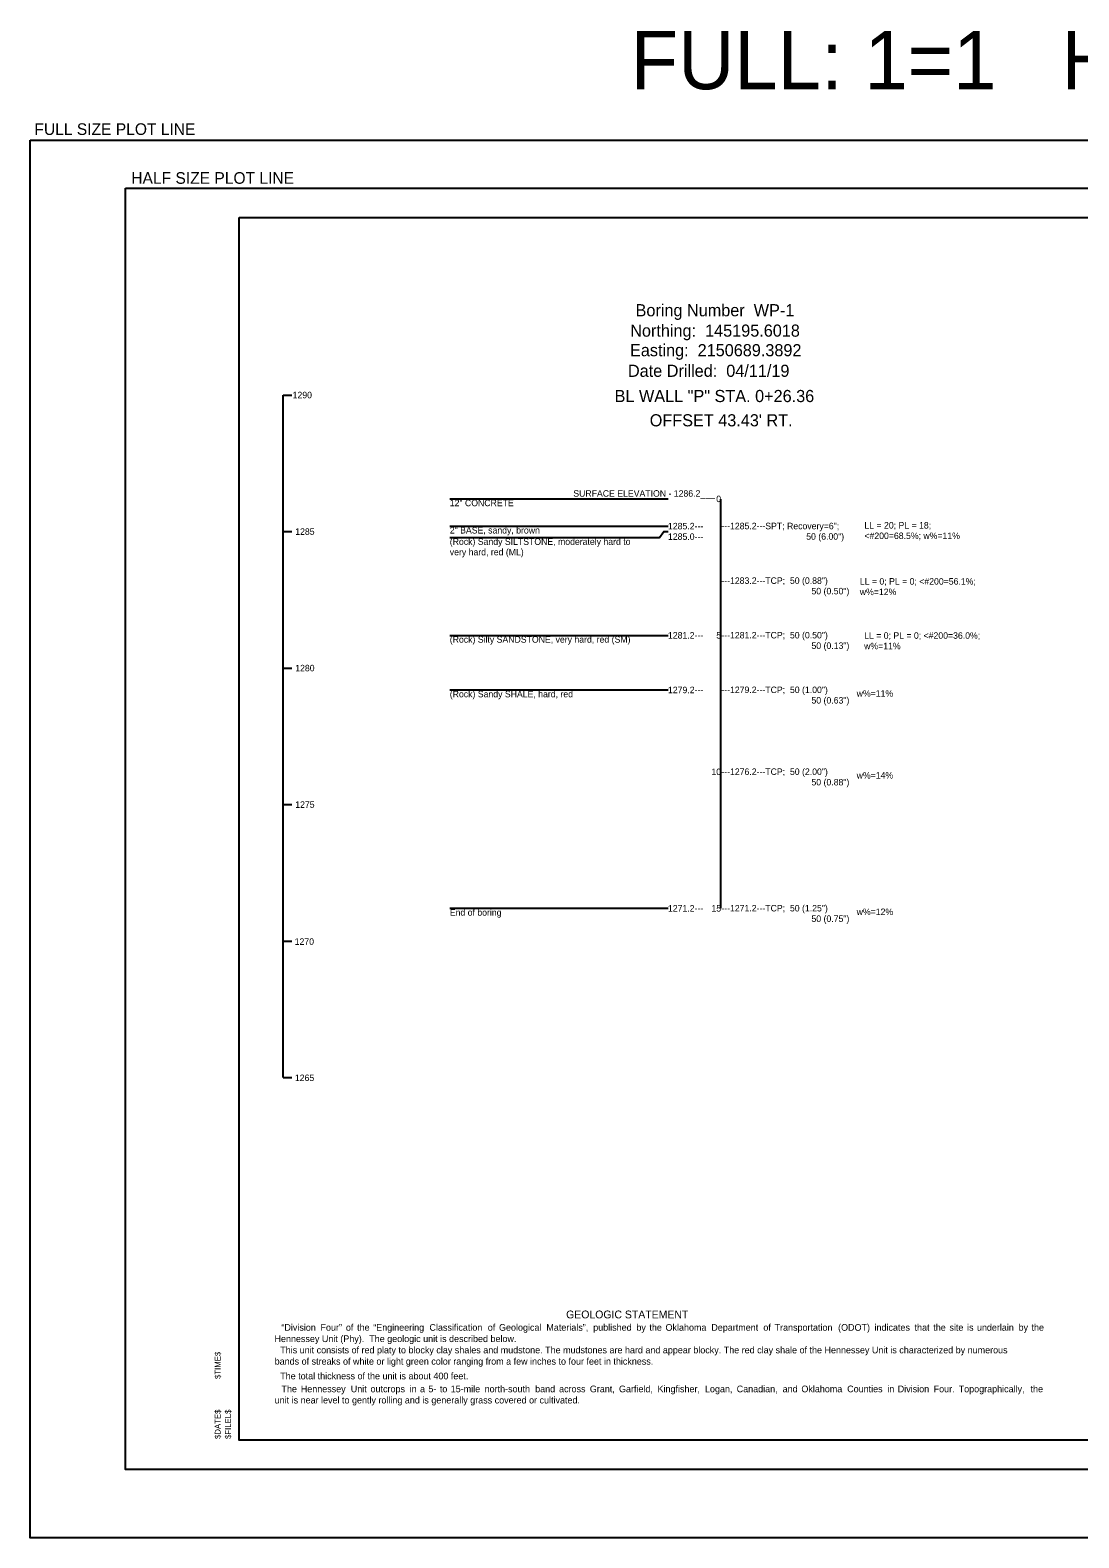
# Model space of a CAD drawing. Extents: x 6.6 to 42.6, y 24.1 to 55.9.
# Drawn here: x 6.62 to 24.62, y 29.97 to 55.86 of the extents above; entities that cross this region are included whole.
import ezdxf

# ---------------------------------------------------------------- set-up
doc = ezdxf.new("R2010")
doc.units = 0
for name, color, linetype in [('S', 7, 'Continuous'), ('SHT_Plot_Shape_Full', 7, 'Continuous'), ('SHT_Plot_Shape_Half', 7, 'Continuous'), ('SHT_Plot_Stamp', 7, 'Continuous'), ('SHT_Sheet_Border', 7, 'Continuous'), ('Text', 7, 'Continuous')]:
    doc.layers.add(name, color=color, linetype=linetype)

# ---------------------------------------------------------------- blocks, each defined once
blk = doc.blocks.new('Stamp_Plot_Stamp')
at = {"layer": 'SHT_Plot_Stamp'}
for s, p in [('$TIME$', (1.695, 1.572)), ('$DATE$', (1.695, 0.542)), ('$FILEL$', (1.873, 0.542))]:
    blk.add_text(s, height=0.1, rotation=90, dxfattribs=at).set_placement(p)

msp = doc.modelspace()

# ---------------------------------------------------------------- linework, layer by layer
msp.add_line((10.966, 37.876), (10.966, 49.594))
for points in [[(10.966, 49.594), (11.116, 49.594)], [(13.827, 47.813), (17.577, 47.813)], [(18.472, 47.81), (18.472, 40.782)], [(10.966, 47.251), (11.116, 47.251)], [(13.827, 47.344), (17.577, 47.344)], [(13.827, 47.149), (17.427, 47.149), (17.502, 47.251), (17.577, 47.251)], [(13.827, 45.469), (17.577, 45.469)], [(10.966, 44.907), (11.116, 44.907)], [(13.827, 44.532), (17.577, 44.532)], [(10.966, 42.563), (11.116, 42.563)], [(13.827, 40.782), (17.577, 40.782)], [(10.966, 40.219), (11.116, 40.219)], [(10.966, 37.876), (11.116, 37.876)]]:
    msp.add_lwpolyline(points)
at = {"layer": 'SHT_Plot_Shape_Full'}
msp.add_lwpolyline([(6.624, 53.971), (42.624, 53.971), (42.624, 29.971), (6.624, 29.971)], close=True, dxfattribs=at)
at = {"layer": 'SHT_Plot_Shape_Half'}
msp.add_lwpolyline([(8.262, 53.146), (42.262, 53.146), (42.262, 31.146), (8.262, 31.146)], close=True, dxfattribs=at)
at = {"layer": 'SHT_Sheet_Border'}
msp.add_lwpolyline([(10.212, 52.646), (41.712, 52.646), (41.712, 31.646), (10.212, 31.646)], close=True, dxfattribs=at)

# ---------------------------------------------------------------- block references
at = {"layer": 'SHT_Plot_Stamp'}
msp.add_blockref('Stamp_Plot_Stamp', (8.198, 31.127), dxfattribs=at)

# ---------------------------------------------------------------- texts
for s, height, p in [('Boring Number  WP-1', 0.2083, (17.016, 50.948)), ('Northing:  145195.6018', 0.20832, (16.924, 50.598)), ('Easting:  2150689.3892', 0.20832, (16.92, 50.262)), ('Date Drilled:  04/11/19', 0.20832, (16.885, 49.908)), ('1290', 0.1116, (11.129, 49.54)), ('BL WALL "P" STA. 0+26.36', 0.20832, (16.656, 49.475)), ("OFFSET 43.43' RT.", 0.20832, (17.259, 49.058)), ('SURFACE ELEVATION - 1286.2___', 0.1116, (15.947, 47.85)), ('12" CONCRETE', 0.1116, (13.827, 47.687)), ('0', 0.112, (18.401, 47.757)), ('1285.2---', 0.1116, (17.572, 47.289)), ('---1285.2---SPT; Recovery=6";', 0.1116, (18.488, 47.291)), ('LL = 20; PL = 18;', 0.1116, (20.944, 47.303)), ('1285', 0.1116, (11.174, 47.195)), ('2" BASE, sandy, brown', 0.1116, (13.827, 47.218)), ('(Rock) Sandy SILTSTONE, moderately hard to', 0.1116, (13.827, 47.023)), ('1285.0---', 0.1116, (17.572, 47.109)), ('50 (6.00")', 0.1116, (19.945, 47.111)), ('<#200=68.5%; w%=11%', 0.1116, (20.944, 47.123)), ('very hard, red (ML)', 0.1116, (13.827, 46.843)), ('---1283.2---TCP;  50 (0.88")', 0.1116, (18.488, 46.353)), ('LL = 0; PL = 0; <#200=56.1%;', 0.1116, (20.865, 46.34)), ('50 (0.50")', 0.1116, (20.035, 46.173)), ('w%=12%', 0.1116, (20.865, 46.16)), ('(Rock) Silty SANDSTONE, very hard, red (SM)', 0.1116, (13.827, 45.343)), ('1281.2---', 0.1116, (17.572, 45.414)), ('5', 0.112, (18.401, 45.414)), ('---1281.2---TCP;  50 (0.50")', 0.1116, (18.488, 45.416)), ('50 (0.13")', 0.1116, (20.035, 45.236)), ('w%=11%', 0.1116, (20.939, 45.23)), ('LL = 0; PL = 0; <#200=36.0%;', 0.1116, (20.939, 45.41)), ('1280', 0.1116, (11.174, 44.851)), ('1279.2---', 0.1116, (17.572, 44.476)), ('---1279.2---TCP;  50 (1.00")', 0.1116, (18.488, 44.478)), ('(Rock) Sandy SHALE, hard, red', 0.1116, (13.827, 44.405)), ('50 (0.63")', 0.1116, (20.035, 44.298)), ('w%=11%', 0.1116, (20.811, 44.416)), ('10', 0.1116, (18.318, 43.07)), ('---1276.2---TCP;  50 (2.00")', 0.1116, (18.488, 43.072)), ('50 (0.88")', 0.1116, (20.035, 42.892)), ('w%=14%', 0.1116, (20.811, 43.009)), ('1275', 0.1116, (11.174, 42.507)), ('End of boring', 0.1116, (13.827, 40.655)), ('1271.2---', 0.1116, (17.572, 40.726)), ('15', 0.1116, (18.318, 40.726)), ('---1271.2---TCP;  50 (1.25")', 0.1116, (18.488, 40.728)), ('50 (0.75")', 0.1116, (20.035, 40.548)), ('w%=12%', 0.1116, (20.811, 40.666)), ('1270', 0.1116, (11.164, 40.154)), ('1265', 0.1116, (11.168, 37.815))]:
    msp.add_text(s, height=height).set_placement(p)
at = {"layer": 'DEFPOINTS'}
for s, p in [('FULL SIZE PLOT LINE', (6.697, 54.062)), ('HALF SIZE PLOT LINE', (8.36, 53.223))]:
    msp.add_text(s, height=0.2, dxfattribs=at).set_placement(p)
at = {"layer": 'S'}
msp.add_text('FULL: 1=1   HALF: 1=2', height=1, dxfattribs=at).set_placement((16.93, 54.847))
at = {"layer": 'Text'}
for s, height, p in [('GEOLOGIC STATEMENT', 0.1344, (15.824, 33.74)), ('Hennessey Unit (Phy).  The geologic unit is described below.', 0.1152, (10.818, 33.333)), ('“Division', 0.1152, (10.937, 33.527)), ('Four”', 0.1152, (11.607, 33.527)), ('of', 0.1152, (12.044, 33.527)), ('the', 0.1152, (12.236, 33.527)), ('“Engineering', 0.1152, (12.513, 33.527)), ('Classification', 0.1152, (13.478, 33.527)), ('of', 0.1152, (14.479, 33.527)), ('Geological', 0.1152, (14.672, 33.527)), ('Materials”,', 0.1152, (15.485, 33.527)), ('published', 0.1152, (16.289, 33.527)), ('by', 0.1152, (17.03, 33.527)), ('the', 0.1152, (17.253, 33.527)), ('Oklahoma', 0.1152, (17.53, 33.527)), ('Department', 0.1152, (18.316, 33.527)), ('of', 0.1152, (19.209, 33.527)), ('Transportation', 0.1152, (19.402, 33.527)), ('(ODOT)', 0.1152, (20.492, 33.527)), ('indicates', 0.1152, (21.117, 33.527)), ('that', 0.1152, (21.805, 33.527)), ('the', 0.1152, (22.126, 33.527)), ('site', 0.1152, (22.403, 33.527)), ('is', 0.1152, (22.706, 33.527)), ('underlain', 0.1152, (22.875, 33.527)), ('by', 0.1152, (23.59, 33.527)), ('the ', 0.1152, (23.812, 33.527)), ('  This unit consists of red platy to blocky clay shales and mudstone. The mudstones are hard and appear blocky. The red clay shale of the Hennessey Unit is characterized by numerous ', 0.1152, (10.831, 33.139)), ('bands of streaks of white or light green color ranging from a few inches to four feet in thickness.', 0.1152, (10.821, 32.945)), ('  The total thickness of the unit is about 400 feet.', 0.1152, (10.831, 32.693)), ('unit is near level to gently rolling and is generally grass covered or cultivated.  ', 0.1152, (10.821, 32.279)), ('The', 0.1152, (10.938, 32.471)), ('Hennessey', 0.1152, (11.269, 32.471)), ('Unit', 0.1152, (12.127, 32.471)), ('outcrops', 0.1152, (12.467, 32.471)), ('in', 0.1152, (13.138, 32.471)), ('a', 0.115, (13.316, 32.471)), ('5-', 0.1152, (13.459, 32.471)), ('to', 0.1152, (13.656, 32.471)), ('15-mile', 0.1152, (13.843, 32.471)), ('north-south', 0.1152, (14.425, 32.471)), ('band', 0.1152, (15.292, 32.471)), ('across', 0.1152, (15.703, 32.471)), ('Grant,', 0.1152, (16.231, 32.471)), ('Garfield,', 0.1152, (16.731, 32.471)), ('Kingfisher,', 0.1152, (17.393, 32.471)), ('Logan,', 0.1152, (18.207, 32.471)), ('Canadian,', 0.1152, (18.752, 32.471)), ('and', 0.1152, (19.54, 32.471)), ('Oklahoma', 0.1152, (19.862, 32.471)), ('Counties', 0.1152, (20.648, 32.471)), ('in', 0.1152, (21.337, 32.471)), ('Division', 0.1152, (21.516, 32.471)), ('Four.', 0.1152, (22.132, 32.471)), ('Topographically,', 0.1152, (22.562, 32.471)), ('the ', 0.1152, (23.796, 32.471))]:
    msp.add_text(s, height=height, dxfattribs=at).set_placement(p)

doc.saveas('drawing.dxf')
